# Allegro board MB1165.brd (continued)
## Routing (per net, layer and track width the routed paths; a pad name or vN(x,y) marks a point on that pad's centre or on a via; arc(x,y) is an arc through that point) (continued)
NETLD3_2: length 82.3
  TOP w0.127: R192.2 v1(72.77,48.13) ; LD3.2 v1(23.39,12.93)
  L3_SIG w0.102: v1(60.12,46.81) 60.58,46.35 68.45,46.35 69.72,47.62 72.26,47.62 v1(72.77,48.13)
  BOTTOM w0.127: v1(23.39,12.93) 23.6,12.73 26.9,12.73 28.7,10.92 42.16,10.92 46.99,15.75 46.99,21.59 51.56,26.16 55.98,26.16 58.45,28.63 58.45,32.41 58.09,32.77 58.09,36.84 60.5,39.25 60.5,46.43 v1(60.12,46.81)
NETLD4_2: length 82.5
  TOP w0.127: v1(21.31,12.98) LD4.2 ; R191.2 v1(70.99,48.13)
  L3_SIG w0.102: v1(70.99,48.13) 69.6,48.13 68.33,46.86 v1(60.96,46.86)
  BOTTOM w0.127: v1(60.96,46.86) 60.93,46.84 60.93,39.22 58.39,36.68 58.39,32.94 58.78,32.56 58.78,27.99 56.57,25.78 51.94,25.78 47.5,21.34 47.5,15.37 42.42,10.29 28.7,10.29 26.75,12.24 22.05,12.24 v1(21.31,12.98)
NETLD5_1: length 1.5
  TOP w0.127: LD5.1 R89.1
NETLD5_2: length 2.4
  TOP w0.254: LD5.2 v1(10.16,110.74)
  BOTTOM w0.254: T7.3 v1(10.16,110.74)
NETLD6_1: length 2.2
  TOP w0.508: LD6.1 v1(16,107.82)
  BOTTOM w0.508: v1(16,107.82) R279.1
NETLD6_2: length 21.9
  TOP w0.254: R112.2 24.14,101.09 25.67,102.62 26.69,102.62 27.2,103.12 U8.10
  TOP w0.508: v1(14.99,109.6) 15.75,110.36 LD6.2 17.09,111.45 U7.3 ; R112.2 R111.2 v1(22.86,102.49)
  L3_SIG w0.508: v1(22.86,102.49) 22.48,102.49 15.37,109.6 v1(14.99,109.6)
NETLD7_1: length 1.5
  TOP w0.127: R108.1 LD7.1
NETLD7_2: length 2.7
  TOP w0.254: v1(13.97,101.85) 13.72,101.85 LD7.2
  BOTTOM w0.254: T8.3 13.84,102.02 13.97,101.9 v1(13.97,101.85)
NETLD8_1: length 1.5
  TOP w0.127: R120.1 LD8.1
NETLD8_2: length 6.2
  TOP w0.508: 10.83,89.79 R121.2 11.43,90.4 ; 10.83,91.44 R119.2 ; R119.2 11.43,92.05 ; R119.2 11.43,90.83 ; LD8.2 9.54,91.44 ; LD8.2 8.89,90.83 ; LD8.2 8.89,92.05 ; 11.62,92.51 U11.3 12.14,93.29
NETLD9_1: length 1.5
  TOP w0.127: LD9.1 R122.1
NETLD9_2: length 2.9
  TOP w0.127: T2.3 13.8,85.51 LD9.2
NETLD10_1: length 1.5
  TOP w0.127: LD10.1 R130.1
NETLD11_1: length 1.7
  TOP w0.127: R187.2 LD11.1
NETLD11_2: length 58.1
  TOP w0.127: LD11.2 v1(13.34,16.51)
  TOP w0.508: U18.8 32.72,55.84 v1(32.64,55.75) 31.88,54.99 R144.2
  BOTTOM w0.127: v1(32.64,55.75) 30.78,53.9 30.78,45.09 33.27,42.6 33.27,33.91 31.5,32.13 31.5,30.07 25.91,24.49 25.91,21.23 21.69,17.02 13.84,17.02 v1(13.34,16.51)
NETLD12_2: length 1.9
  TOP w0.127: LD12.2 15,13.7 R188.2
NETLD12_3: length 1.9
  TOP w0.127: LD12.3 16.5,13.73 R189.2
NETLD12_4: length 5.3
  TOP w0.127: R190.1 17.78,10.45 LD12.4
NETR2_2: length 2.6
  TOP w0.508: U1.1 139.6,168.51 R2.2
NETR3_2: length 7.9
  TOP w0.127: SW1.2 49.53,166.37 46.23,166.37 44.96,167.64 R3.2
NETR6_1: length 7.9
  TOP w0.127: SW2.2 49.28,165.48 44.83,165.48 R6.1
NETR21_1: length 13.9
  TOP w0.127: R22.1 R21.1 84.58,147.57 84.58,144.82 v3(84.61,144.82) ; v5(81.21,140.09) U4.E5
  L3_SIG w0.102: v3(84.61,144.82) 84.6,144.82 84.58,144.81 84.58,142.96 82.87,141.24 82.59,141.24 82.4,141.05 82.4,140.72 82.17,140.49 81.61,140.49 v5(81.21,140.09)
NETR23_1: length 14.2
  TOP w0.102: 76.81,144.02 U4.K1
  TOP w0.127: 76.81,144.02 76.81,146.33 76.07,147.07 73.66,147.07 71.88,148.84 R23.1
NETR25_1: length 13.1
  TOP w0.127: U4.K2 76.73,142.09 76.45,142.37 76.45,142.72 76.44,142.73 76.44,143.04 76.45,143.05 76.45,144.02 76.07,144.4 74.93,144.4 71.75,147.57 67.31,147.57 R25.1
NETR26_1: length 3.1
  TOP w0.203: R26.1 137.47,146.56 X3.1
NETR27_1: length 12.3
  TOP w0.127: U4.L2 75.61,142.49 75.61,143.26 75.21,143.66 74.4,143.66 73.79,144.27 73.28,144.27 72.9,144.65 72.9,145.8 71.5,147.19 68.58,147.19 68.2,146.81 R27.1
NETR28_1: length 2.2
  TOP w0.127: R29.2 R28.1
NETR28_2: length 174.5
  TOP w0.127: v1(22.23,144.53) 16.64,144.53 R28.2
  L3_SIG w0.102: RV1.2 37.72,5.59 46.35,14.22 46.35,25.65 41.78,30.23 41.15,30.23 38.99,32.38 37.24,32.38 32.77,36.86 32.77,42.42 30.86,44.32 30.86,61.09 28.19,63.75 28.19,70.48 27.43,71.25 27.43,85.6 26.49,86.54 v1(26.49,92.43)
  BOTTOM w0.127: v1(26.49,92.43) 29.31,92.43 35.56,98.68 35.56,117.22 32,120.78 32,124.59 27.51,129.08 27.51,136.07 24.77,138.81 24.77,143.13 23.37,144.53 v1(22.23,144.53)
NETR32_1: length 13
  TOP w0.127: U4.B1 83.21,143.18 83.92,143.89 86.74,143.89 88.77,145.92 R32.1 89.79,146.56 89.66,146.69 SB3.2 SB4.2 SB5.2
NETR34_1: length 81.5
  TOP w0.127: v1(127.06,102.43) 127.19,102.43 SB18.2 SB19.2 129.57,101.63 129.57,103.1 SB17.2 ; U4.B2 83.21,142.37 83.58,142.73 83.58,143.01 83.95,143.38 87.12,143.38 88.39,144.65 R34.1 90.42,145.29 91.06,145.29 91.95,146.18 99.95,146.18 v1(100.2,145.92)
  L3_SIG w0.102: v1(127.06,102.43) 125.54,102.43 120.14,107.82 116.08,107.82 105.41,118.49 v1(105.28,118.49)
  BOTTOM w0.127: v1(100.2,145.92) 100.36,145.92 100.97,145.31 100.97,134.24 104.27,130.94 104.27,124.46 105.28,123.44 v1(105.28,118.49)
NETR35_1: length 11.1
  TOP w0.127: SB6.2 93.47,143.76 ; U4.A1 88.96,142.89 89.46,143.38 R35.1 90.3,143.89 93.09,143.89 93.22,143.76
NETR37_1: length 13.4
  TOP w0.127: 93.47,140.44 92.86,140.44 91.72,141.58 90.02,141.58 89.53,141.1 SB9.2 89.53,140.59 89.66,140.46 R37.1 89.25,139.19 86.74,141.7 84.82,141.7 84.43,142.09 U4.A2
NETR38_1: length 32.4
  TOP w0.127: U4.A3 84.04,141.32 86.52,141.32 88.33,139.51 88.33,139.26 R38.1 90.17,138.43 91.57,138.43 91.85,138.71 SB11.2 93.47,138.35 93.94,137.88 97.96,137.88 v1(98.93,136.91)
  L3_SIG w0.102: v1(111.82,137.97) 107.75,137.97 106.68,136.91 v1(98.93,136.91)
  BOTTOM w0.127: R238.2 111.24,138.56 v1(111.82,137.97)
NETR40_1: length 8.2
  TOP w0.127: U4.B6 83.58,139.26 84.16,139.26 84.23,139.19 84.81,139.19 84.93,139.06 86.08,139.06 86.41,138.73 86.41,137.92 86.64,137.69 87.17,137.69 88.14,136.73 88.72,136.73 88.93,136.53 R40.1
NETR41_1: length 9.4
  TOP w0.127: U4.B7 83.63,138.51 84.38,138.51 85.5,137.39 87.02,137.39 88.09,136.32 88.09,135.15 88.52,134.72 88.52,134.49 89.03,133.99 R41.1
NETR42_1: length 3.1
  TOP w0.127: R42.1 124.71,128.4 125.35,127.76 125.48,127.76 126.27,126.97 U6.46
NETR43_1: length 2.7
  TOP w0.127: U6.45 126.77,127.23 125.98,128.02 R43.1
NETR43_2: length 20.7
  TOP w0.127: v1(124.61,140.39) 124.61,136.37 125.35,135.64 125.35,130.68 R43.2
  L3_SIG w0.102: v1(124.61,140.39) 120.7,140.39 v1(117.35,137.03)
  BOTTOM w0.127: v1(117.35,137.03) 116.94,137.44 SB55.2
NETR44_1: length 2.4
  TOP w0.127: U6.44 127.27,128.51 R44.1
NETR44_2: length 127.5
  TOP w0.127: R44.2 125.83,131.47 125.83,136.58 125.35,137.06 125.35,156.24 125.83,156.72 125.83,157.89 v1(125.09,158.62)
  L3_SIG w0.102: v1(102.36,157.61) 102.87,157.61 103.89,158.62 v1(125.09,158.62)
  BOTTOM w0.127: SB73.2 48.73,130.14 48.73,131.1 50.7,133.07 50.7,138.41 55.41,143.12 55.41,148.76 60.48,153.83 64.8,153.83 68.2,157.23 69.47,157.23 70.15,157.91 80.52,157.91 80.92,158.32 93.42,158.32 93.83,158.72 101.24,158.72 v1(102.36,157.61)
NETR45_1: length 2.7
  TOP w0.127: R45.1 128.52,127.89 127.76,127.13 127.76,126.15 U6.43
NETR45_2: length 147.3
  TOP w0.127: R45.2 126.36,132.21 126.36,152.43 v1(126.85,152.91)
  BOTTOM w0.127: SB53.2 37.47,142.9 36.83,143.54 36.83,158.5 42.04,163.7 42.04,167 44.32,169.29 86.61,169.29 87.12,168.78 87.63,168.78 88.14,169.29 110.46,169.29 v1(126.85,152.91)
NETR46_1: length 2.6
  TOP w0.127: U6.39 129.77,127.1 130.18,127.51 R46.1
NETR46_2: length 113.6
  TOP w0.127: v1(127.83,132.84) 128.84,131.83 129.16,131.83 130.18,130.81 R46.2
  BOTTOM w0.127: SB45.1 49.02,144.53 51.61,147.12 51.61,150.42 59.94,158.75 63.37,158.75 66.42,161.8 82.14,161.8 83.16,160.78 91.59,160.78 92.46,161.65 97.77,161.65 98.42,162.31 105.08,162.31 107.95,159.44 113.36,159.44 119.13,153.67 119.13,152.4 127.64,143.89 127.64,133.03 v1(127.83,132.84)
NETR47_1: length 2.9
  TOP w0.127: R47.1 131.44,128.27 130.27,127.09 U6.38
NETR47_2: length 111.8
  TOP w0.127: v1(128.14,134.11) 128.14,133.81 131.44,130.51 R47.2
  BOTTOM w0.127: v1(128.14,134.11) 128.14,144.15 119.63,152.65 119.63,154.05 113.23,160.45 109.25,160.45 106.32,163.37 65.07,163.37 64.39,162.69 61.85,162.69 61.34,162.18 58.55,162.18 49.35,152.98 49.35,150.95 SB39.1
NETR48_1: length 16.8
  TOP w0.127: U4.P8 73.23,137.67 70.51,137.67 64.52,131.67 R48.1
NETR49_1: length 15.4
  TOP w0.127: R49.1 65.53,131.59 70.85,136.91 71.79,136.91 71.8,136.92 73.18,136.92 U4.P9
NETR50_1: length 14.8
  TOP w0.127: R50.1 66.55,131.53 71.11,136.09 74.01,136.09 U4.N9
NETR51_1: length 12.6
  TOP w0.127: R51.1 67.56,131.47 71.38,135.29 73.21,135.29 U4.P10
NETR52_1: length 10.9
  TOP w0.127: U4.P11 73.22,134.49 72.64,134.49 71.88,133.73 71.45,133.73 68.58,130.86 R52.1
NETR53_2: length 7
  TOP w0.127: R53.2 70.99,128.12 72.64,129.77 72.64,130.94 73.21,131.5 73.21,132.09 U4.P14
NETR54_2: length 6.7
  TOP w0.127: U4.N14 74.02,132.09 74.02,131.29 73.41,130.68 73.41,129.22 72.39,128.21 R54.2
NETR55_2: length 5.7
  TOP w0.127: U4.M15 75.21,130.58 74.17,129.54 74.17,128.91 73.79,128.52 R55.2
NETR56_1: length 5.6
  TOP w0.127: R56.1 74.96,126.85 74.96,129.19 76.01,130.24 U4.L15
NETR57_1: length 2.2
  TOP w0.127: R57.1 121.92,124.46 122,124.54 U6.1
NETR57_2: length 115.7
  TOP w0.127: v1(120.65,137.03) 120.65,136.09 121.54,135.2 R57.2
  BOTTOM w0.127: v1(120.65,137.03) 117.2,140.49 113.31,140.49 112.36,141.44 111.75,141.44 110.62,142.57 110.62,154.18 107.89,156.91 107.89,158.31 104.9,161.29 98.81,161.29 98.37,160.86 92.61,160.86 91.85,160.1 81.76,160.1 81.1,160.76 77.32,160.76 76.63,160.07 68.4,160.07 68.05,159.72 66.42,159.72 63.3,156.59 60.07,156.59 53.16,149.68 53.16,144.18 48.88,139.79 48.88,139.43 SB54.2
NETR58_1: length 18.6
  TOP w0.127: R58.1 65.02,123.83 65.02,131.62 70.69,137.29 U4.R8
NETR59_1: length 17.3
  TOP w0.127: U4.R9 72.48,136.49 72.44,136.53 71,136.53 66.04,131.56 66.04,123.83 R59.1
NETR60_1: length 15.9
  TOP w0.127: R60.1 67.06,123.83 67.06,131.5 71.24,135.69 U4.R10
NETR61_1: length 14.2
  TOP w0.127: R61.1 68.07,123.83 68.07,130.94 71.37,134.24 72.01,134.24 72.66,134.89 U4.R11
NETR62_1: length 12.8
  TOP w0.127: U4.R12 72.07,133.35 71.68,133.35 69.01,130.68 69.01,129.03 69.09,128.96 69.09,123.83 R62.1
NETR63_2: length 9.5
  TOP w0.127: U4.P15 73.61,131.39 73.03,130.81 73.03,129.49 71.5,127.97 71.5,124.59 70.99,124.08 R63.2
NETR64_2: length 9.2
  TOP w0.127: R64.2 72.39,123.83 72.9,124.33 72.9,128.18 73.79,129.07 73.79,130.57 74.41,131.19 U4.N15
NETR65_1: length 10.1
  TOP w0.127: R65.1 73.79,123.95 74.3,124.46 74.3,128.49 74.55,128.75 74.55,129.38 75.62,130.45 75.62,132.09 U4.L14
NETR66_1: length 9.4
  TOP w0.127: U4.K15 76.82,131.67 76.82,130.29 75.41,128.88 75.41,127.56 75.82,127.16 75.82,123.95 R66.1
NETR67_1: length 3
  TOP w0.254: R67.1 135.02,123.04 U6.33
NETR68_2: length 127
  TOP w0.127: U6.7 121.54,121.54 R68.2 v1(122.28,120.8) ; v1(58.04,43.18) 58.51,42.71 U22.26
  L3_SIG w0.102: v1(58.04,43.18) 60.1,45.24 79.12,45.24 82.91,49.02 83.74,49.02 100.79,66.07 100.79,69.39 102.55,71.16 105.4,71.16 107.54,73.3 107.54,75.16 109.73,77.34 109.73,81.15 110.29,81.71 110.29,87.73 116.38,93.83 v1(116.38,94.03)
  BOTTOM w0.127: v1(116.38,94.03) 116.23,94.18 116.23,112.14 123.04,118.95 123.04,120.29 122.53,120.8 v1(122.28,120.8)
NETR69_1: length 138.2
  TOP w0.127: U6.30 133.22,121.54 v1(133.6,121.16) 134.11,121.16 R69.1
  BOTTOM w0.127: v1(133.6,121.16) 134.11,121.67 134.11,122.68 133.1,123.7 133.1,126.44 129.59,129.95 129.59,145.14 113.18,161.54 109.98,161.54 107.44,164.08 64.77,164.08 64.14,163.45 57.28,163.45 51.94,158.12 42.29,158.12 38.99,154.81 38.99,150.6 SB40.1
NETR71_1: length 4.4
  TOP w0.127: R71.1 134.24,118.24 134.24,118.77 132.97,120.04 U6.27
NETR74_2: length 4.7
  TOP w0.254: R74.2 R78.1 v1(12.95,111.25)
  BOTTOM w0.254: T7.1 12.51,111.69 v1(12.95,111.25)
NETR75_1: length 2.6
  TOP w0.127: R75.1 128.77,116.07 U6.20
NETR76_1: length 2.3
  TOP w0.127: R76.1 129.27,115.21 U6.21
NETR77_2: length 3.4
  TOP w0.127: R77.2 132.08,117.19 131.83,117.44 U6.24
NETR82_1: length 5.1
  TOP w0.127: R82.1 33.27,109.98 32.26,109.98 31.62,109.35 31.62,108.2 31.21,107.8 U8.24
NETR84_1: length 7.2
  TOP w0.102: 76.45,107.95 76.45,105.83 U9.F2
  TOP w0.127: R84.1 R85.1 76.45,109.98 76.45,107.95
NETR88_2: length 5.8
  TOP w0.508: U7.4 19.87,112.59 20.57,111.89 SB16.2 R88.2 SB15.2
NETR91_2: length 2.6
  TOP w0.127: R91.2 26.58,108.58 U8.32
NETR94_1: length 3.4
  TOP w0.127: R94.1 33.52,106.29 U8.21
NETR95_1: length 2
  TOP w0.254: U8.4 24.39,106.29 R95.1
NETR97_2: length 5.5
  TOP w0.254: v1(12.95,106.68) R97.2 R100.2
  BOTTOM w0.254: T8.1 11.75,105.48 v1(12.95,106.68)
NETR98_1: length 3.3
  TOP w0.127: R98.1 33.78,105.8 U8.20
NETR99_1: length 66.2
  TOP w0.102: v4(82.68,102.37) U9.A5 ; v5(63.79,72.16) U16.G5
  TOP w0.127: v1(86.87,103.38) R99.1
  L3_SIG w0.102: v4(82.68,102.37) 83.3,102.99 86.48,102.99 v1(86.87,103.38)
  BOTTOM w0.127: v5(63.79,72.16) 63.42,72.53 62.47,72.53 61.75,73.25 61.75,75.54 61.87,75.67 63.12,75.67 63.25,75.79 63.25,90.4 63.37,90.53 64.89,90.53 65.02,90.65 65.02,100.61 73.38,108.97 79.15,108.97 80.48,107.63 80.48,106.14 80,105.66 80,104.7 82.34,102.37 v4(82.68,102.37)
NETR101_2: length 10
  TOP w0.127: U8.9 25.53,103.62 25.03,103.12 22.35,103.12 21.46,104.01 R101.2 18.8,103.63 18.8,103.21 18.29,102.7 T1.3
NETR109_1: length 4.5
  TOP w0.127: R109.1 32.38,103.63 32.38,104.27 31.86,104.8 U8.18
NETR111_1: length 99.8
  TOP w0.127: v1(26.57,96.11) 25.3,96.11 22.86,98.55 R111.1 ; U22.29 57.02,37.99 57.02,36.96 56.59,36.53 56.59,33.39 v1(57.02,32.96)
  L3_SIG w0.102: v1(57.02,32.96) 57.02,32.89 56.69,32.56 52.37,32.56 49.73,29.92 44.6,29.92 40.26,34.26 38,34.26 34.42,37.85 34.42,44.58 33.66,45.34 33.66,61.21 32.05,62.81 32.05,69.55 29.18,72.42 29.18,93.5 v1(26.57,96.11)
NETR113_1: length 2.9
  TOP w0.127: R113.1 29.97,101.22 29.2,101.99 U8.14
NETR114_1: length 5.5
  TOP w0.127: T1.1 17.34,98.87 R115.2 18.29,97.92 19.94,97.92 R114.1
NETR116_2: length 6.2
  TOP w0.508: R116.2 12.29,97.28 ; R116.2 11.07,97.28 ; R116.2 11.68,96.68 ; U11.4 12.14,95.69 ; U11.4 11.1,95.69 ; U11.4 11.62,94.91 ; U11.4 11.62,96.46 ; 13.21,96.68 R117.1 ; R117.1 12.6,97.28 ; R117.1 13.82,97.28
NETR117_2: length 106.8
  TOP w0.127: U22.17 58.76,32.9 v1(57.99,32.13) ; R117.2 v1(14.99,98.81)
  L3_SIG w0.102: v1(14.99,98.81) 22.99,98.81 28.91,92.89 28.91,72.3 31.72,69.48 31.72,62.76 33.4,61.09 33.4,45.21 34.16,44.45 34.16,37.72 37.85,34.04 40.11,34.04 44.55,29.59 53.85,29.59 56.52,32.26 57.86,32.26 v1(57.99,32.13)
NETR119_1: length 100.8
  TOP w0.127: U22.16 59.02,32.41 v1(57.99,31.37) ; R119.1 14.15,91.44 18.29,87.3 v1(28.09,87.3)
  L3_SIG w0.102: v1(28.09,87.3) 28.6,86.79 28.6,72.19 31.39,69.39 31.39,62.71 32.13,61.98 32.13,45.85 33.91,44.07 33.91,37.59 37.74,33.76 39.98,33.76 44.42,29.31 54.08,29.31 56.64,31.88 57.48,31.88 v1(57.99,31.37)
NETR126_2: length 6.7
  TOP w0.127: T2.1 10.67,83.84 10.67,82.42 11.43,81.66 R127.2 R126.2
NETR134_1: length 7.8
  TOP w0.102: U16.B5 68.29,72.16 68.29,71.54 68.71,71.12 68.71,69.09
  TOP w0.127: R135.1 R134.1 68.71,66.8 68.71,69.09
NETR140_1: length 1.6
  TOP w0.254: R140.1 39.12,58.29 R141.2
NETR140_2: length 2.3
  TOP w0.254: R140.2 37.49,57.68 U18.5
NETR142_1: length 126.1
  TOP w0.127: v1(58.98,35.26) 57.51,36.72 U22.28 ; R142.1 141.86,55.88 139.83,53.85 R143.1 138.94,53.98 138.15,54.76 v1(133.4,54.76)
  BOTTOM w0.127: v1(133.4,54.76) 133.4,47.55 126.75,40.89 126.75,23.22 125.76,22.23 110.49,22.23 102.87,29.84 70.99,29.84 69.6,31.24 61.34,31.24 60.33,32.26 60.33,33.63 58.98,34.98 v1(58.98,35.26)
NETR155_1: length 2
  TOP w0.127: R155.1 62.12,34.9 U22.21
NETR155_2: length 2.1
  TOP w0.127: R155.2 61.82,35.41 U22.22
NETR156_1: length 2.5
  TOP w0.127: R156.1 50.68,32.9 U22.44
NETR157_2: length 2.9
  TOP w0.127: R157.2 32.9,32.9 U21.44
NETR158_1: length 4.3
  TOP w0.127: R159.1 49.78,29.84 R158.1 50.42,31.62 50.42,32.13 50.69,32.41 U22.45
NETR163_1: length 5.4
  TOP w0.127: R163.1 51.05,27.3 51.31,27.05 R164.2 52.2,27.05 52.2,27.43 52.96,28.19 53.63,28.19 54.01,28.57 U22.2
NETR163_2: length 160.6
  TOP w0.127: v1(47.24,30.99) 47.24,28.5 49.58,26.16 49.91,26.16 R163.2 50.29,25.4 57.02,18.67 57.02,11.05
  L3_SIG w0.102: v1(36.96,119.38) 37.21,119.63 37.21,123.44 34.8,125.86 34.8,137.92 35.43,138.56 35.43,144.25 36.2,145.01 36.2,145.85 37.72,147.37 v1(39.1,147.37)
  BOTTOM w0.127: SB44.1 40.51,145.96 v1(39.1,147.37) ; v1(47.24,30.99) 51.94,35.69 51.94,39.62 59.41,47.09 59.41,60.43 48.69,71.15 48.69,78.38 39.27,87.81 39.27,107.21 37.39,109.09 37.39,118.95 v1(36.96,119.38)
NETR167_2: length 3.5
  TOP w0.127: R167.2 33.54,27.18 34.56,28.19 35.31,28.19 35.72,28.61 U21.2
NETR168_2: length 2.7
  TOP w0.127: U21.3 36.22,28.6 R168.2
NETR171_1: length 9.9
  TOP w0.127: U23.D4 117.86,28.58 v2(118.11,28.83) U23.D5 ; R171.1 124.26,25.22 v1(124.26,25.02)
  L3_SIG w0.102: v1(124.26,25.02) 123.04,25.02 120.37,27.69 118.76,27.69 118.44,28 118.44,28.5 v2(118.11,28.83)
NETR172_2: length 9.5
  TOP w0.127: U23.F3 v2(119.11,28.33) ; v1(125.86,25.27) 126.11,25.27 R172.2
  L3_SIG w0.102: v2(119.11,28.33) 119.48,27.97 120.9,27.97 123.14,25.73 125.4,25.73 v1(125.86,25.27)
NETR178_2: length 5
  TOP w0.127: U23.G2 v2(119.61,27.33) ; R178.2 122.43,24.82 v1(122.4,24.85)
  L3_SIG w0.102: v1(122.4,24.85) 119.92,27.33 v2(119.61,27.33)
NETR179_2: length 5.5
  TOP w0.127: R179.2 123.83,24.38 121.13,27.08 U23.H1
NETR182_2: length 2.2
  TOP w0.127: T4.2 18.99,21.53 18.54,21.08 R182.2
NETR186_1: length 3.4
  TOP w0.127: R186.1 122.43,15.49 122.43,16 122.68,16.26 123.19,16.26 123.78,15.66 U25.2
NETR214_2: length 19.5
  TOP w0.102: U4.H3 77.99,140.87 v5(77.22,140.87)
  BOTTOM w0.127: R214.2 67.94,152.27 74.17,146.05 74.17,145.67 75.06,144.78 75.07,144.78 75.44,144.41 75.44,143 75.18,142.75 75.18,141.59 75.46,141.32 75.75,141.32 76.04,141.03 76.04,140.73 76.29,140.49 76.94,140.49 77.22,140.77 v5(77.22,140.87)
NETR216_1: length 3.7
  TOP w0.127: U3.8 v1(32.89,152.78)
  BOTTOM w0.127: R216.1 v1(32.89,152.78)
NETR217_2: length 4.2
  TOP w0.127: v1(28.96,152.78) U3.9
  BOTTOM w0.127: R217.2 v1(28.96,152.78)
NETR221_1: length 18.1
  TOP w0.127: v5(76.41,141.69) U4.K3
  BOTTOM w0.127: v5(76.41,141.69) 76.41,141.75 77.09,143.32 77.09,144.94 78.33,146.18 83.57,146.18 85.09,147.7 89.03,147.7 R221.1
NETR222_1: length 8.4
  TOP w0.127: v5(73.66,145.03) 74.68,144.02 75.56,144.02 76.01,143.57 U4.L1
  BOTTOM w0.127: v5(73.66,145.03) 73.66,145.16 R222.1
NETR223_1: length 15.9
  TOP w0.127: v5(77.21,142.49) U4.J2
  BOTTOM w0.127: R223.1 89.66,147.32 85.34,147.32 83.82,145.8 80.84,145.8 80.14,145.1 80.14,144.23 79.46,143.56 77.93,143.56 77.21,142.84 v5(77.21,142.49)
NETR226_1: length 15.7
  TOP w0.127: U4.H2 78.36,142.09 v5(77.99,142.46)
  BOTTOM w0.127: R226.1 89.28,145.92 88.27,146.94 85.6,146.94 84.02,145.36 80.94,145.36 80.52,144.94 80.52,144.08 79.65,143.21 78.05,143.21 77.85,143 77.85,142.6 v5(77.99,142.46)
NETR227_1: length 4.1
  TOP w0.127: v1(32.41,145.03) 32.64,145.03 33.78,143.89 U3.1
  BOTTOM w0.127: v1(32.41,145.03) R227.1
NETR228_2: length 4.2
  TOP w0.127: U3.15 28.7,145.16 v1(28.83,145.03)
  BOTTOM w0.127: R228.2 v1(28.83,145.03)
NETR230_1: length 12.9
  TOP w0.127: v5(79.61,142.49) U4.G2
  BOTTOM w0.127: v5(79.61,142.49) 79.61,142.5 80.9,143.79 80.9,144.78 81.09,144.97 83.8,144.97 84.14,144.64 84.14,144.59 84.5,144.23 89.37,144.23 R230.1
NETR232_1: length 10.3
  TOP w0.127: v5(81.21,142.49) U4.E2
  BOTTOM w0.127: R232.1 88.56,142.24 87,143.81 84.14,143.81 83.64,143.31 82.6,143.31 82.19,142.9 81.86,142.9 81.45,142.49 v5(81.21,142.49)
NETR233_2: length 143.4
  TOP w0.127: v1(122.1,155.57) 122.1,142.52 119.91,140.34 119.91,124.13 120.62,123.42 120.62,122.96 121.04,122.54 U6.5
  BOTTOM w0.127: R233.2 37.85,143.89 37.85,155.45 42.04,159.64 51.31,159.64 58.17,166.5 110.74,166.5 121.67,155.57 v1(122.1,155.57)
NETR235_2: length 29
  TOP w0.127: U6.4 122.68,123.04 122.52,122.89 121.46,122.89 v1(121.08,123.27)
  BOTTOM w0.127: v1(121.08,123.27) 121.34,123.52 121.34,127.13 120.52,127.94 120.52,134.78 119.33,135.97 119.33,137.11 117.35,139.09 111.89,139.09 111.38,139.6 109.83,139.6 R235.2
NETR236_1: length 11.2
  TOP w0.127: v5(82.01,142.49) U4.D2
  BOTTOM w0.127: R236.1 89.66,139.32 87.5,141.48 87.5,142.75 86.82,143.43 84.12,143.43 83.72,143.03 82.78,143.03 82.24,142.49 v5(82.01,142.49)
NETR237_1: length 10.2
  TOP w0.127: U4.L3 v5(75.61,141.69)
  L3_SIG w0.102: v1(68.2,139.7) 69.09,140.59 72.14,140.59 72.82,141.27 75.23,141.27 75.61,141.65 v5(75.61,141.69)
  BOTTOM w0.127: v1(68.2,139.7) 67.56,139.06 R237.1
NETR238_1: length 30
  TOP w0.127: U6.6 122.76,122.04 122.66,122.15 120.83,122.15 120.14,122.83 v1(120.14,123.19)
  BOTTOM w0.127: v1(120.14,123.19) 120.14,123.88 120.9,124.64 120.9,127.02 120.14,127.78 120.14,134.62 118.71,136.06 118.71,137.07 117.07,138.71 111.71,138.71 111.2,139.22 109.88,139.22 R238.1
NETR239_2: length 11.8
  TOP w0.127: v5(75.61,140.09) U4.L5
  BOTTOM w0.127: R239.2 67.31,137.79 70.26,140.74 73.3,140.74 73.86,141.3 74.96,141.3 75.23,141.02 75.23,140.72 75.61,140.34 v5(75.61,140.09)
NETR240_2: length 10.5
  TOP w0.127: v5(82.01,140.89) U4.D4
  BOTTOM w0.127: R240.2 89.59,137.03 88.39,138.23 88.39,138.84 87.26,139.97 84.44,139.97 83.13,141.27 82.4,141.27 v5(82.01,140.89)
NETR241_2: length 11.6
  TOP w0.127: v5(81.21,140.89) U4.E4
  BOTTOM w0.127: R241.2 88.42,137.26 88.42,137.62 88.01,138.02 88.01,138.66 87.08,139.59 83.93,139.59 83.06,140.46 81.63,140.46 v5(81.21,140.89)
NETR242_2: length 17.9
  TOP w0.127: U6.2 122.39,124.04 122.17,123.83 120.95,123.83 120.41,124.37 v1(120.41,125.3)
  BOTTOM w0.127: R242.2 118.11,135.89 119.76,134.24 119.76,127.56 120.41,126.91 v1(120.41,125.3)
NETR243_2: length 17.3
  TOP w0.127: v5(77.24,140.08) 77.61,140.45 U4.J4
  BOTTOM w0.127: SB63.1 65.02,135.89 66.67,135.89 R243.2 69.47,137.67 69.47,139.32 70.64,140.49 74.96,140.49 75.18,140.26 75.18,139.95 75.44,139.7 76.56,139.7 76.94,140.08 v5(77.24,140.08)
NETR244_2: length 12.9
  TOP w0.127: SB12.1 88.57,136.22 v1(88.54,136.22) ; U4.D5 v5(82.01,140.09)
  BOTTOM w0.127: R244.2 89.03,135 88.54,135.48 v1(88.54,136.22) 87.6,137.16 87.6,138.51 86.91,139.2 83.43,139.2 82.93,139.7 82.4,139.7 v5(82.01,140.09)
NETR245_1: length 11.4
  TOP w0.127: v5(74.01,139.29) U4.N6
  BOTTOM w0.127: v5(74.01,139.29) 73.77,139.29 73.2,139.85 71.09,139.85 70.36,139.12 70.36,138.81 70.36,137.44 69.09,136.17 69.09,135.41 67.79,134.11 R245.1
NETR246_2: length 21
  TOP w0.127: v5(77.21,141.69) U4.J3
  BOTTOM w0.127: v5(77.21,141.69) 77.62,141.27 77.62,139.9 77.43,139.71 77.03,139.71 76.83,139.52 76.83,139.09 76.63,138.89 75.46,138.89 75.21,139.14 75.21,139.47 74.98,139.7 73.81,139.7 73.28,140.23 70.93,140.23 69.86,139.17 69.86,137.55 68.69,136.39 68.69,135.62 67.82,134.75 65.79,134.75 65.15,134.11 R246.2
NETR247_2: length 12
  TOP w0.127: v5(82.01,139.29) U4.D6
  BOTTOM w0.127: v5(82.01,139.29) 82.38,138.91 83.08,138.91 83.17,138.82 86.7,138.82 87.22,138.3 87.22,136.88 88.01,136.09 88.01,134.87 88.9,133.99 R247.2
NETR248_1: length 11.9
  TOP w0.127: v5(74.81,139.29) U4.M6
  BOTTOM w0.127: v5(74.81,139.29) 74.38,138.86 73.86,138.86 73.28,138.28 73.28,137.32 72.99,137.03 71.06,137.03 69.98,135.95 69.98,135.13 67.69,132.84 R248.1
NETR249_1: length 13.5
  TOP w0.127: v5(73.21,139.29) U4.P6
  BOTTOM w0.102: v5(73.21,139.29) 73.03,139.47 71.63,139.47
  BOTTOM w0.127: 71.63,139.47 71.25,139.47 70.74,138.96 70.74,137.29 69.47,136.02 69.47,135.25 67.56,133.35 65.79,133.35 65.28,132.84 R249.1
NETR250_1: length 12.3
  TOP w0.127: v5(74.81,138.49) U4.M7
  BOTTOM w0.127: R250.1 67.82,131.44 70.74,134.37 70.74,135.64 71.37,136.27 72.87,136.27 73.79,137.19 73.79,137.95 73.95,138.11 74.44,138.11 v5(74.81,138.49)
NETR251_1: length 14
  TOP w0.127: v5(74.01,138.49) U4.N7
  BOTTOM w0.127: R251.1 65.28,131.44 66.04,132.21 67.69,132.21 70.36,134.87 70.36,135.79 71.22,136.65 72.93,136.65 73.53,137.25 73.53,138.05 73.97,138.49 v5(74.01,138.49)
NETR254_1: length 67
  BOTTOM w0.127: SB27.2 92.61,156.16 91.54,157.23 81.76,157.23 81.38,156.84 70.99,156.84 69.7,155.55 67.92,155.55 65.38,153.01 60.93,153.01 56.18,148.26 56.18,142.8 51.51,138.13 51.51,130.51 48.51,127.51 R254.1
NETR256_1: length 11.2
  TOP w0.127: v5(76.38,133.71) 76.8,133.29 U4.K13
  BOTTOM w0.127: v5(76.38,133.71) 76.38,133.86 76.02,134.21 76.02,134.6 75.76,134.86 75.42,134.86 75.18,134.62 75.18,133.53 75.46,133.25 75.46,132.31 75.41,132.26 75.41,127.53 R256.1
NETR257_1: length 8.1
  TOP w0.127: v5(74.81,133.69) U4.M12
  BOTTOM w0.127: R257.1 74.88,126.92 74.88,132.13 75.2,132.45 75.2,133.06 74.81,133.44 v5(74.81,133.69)
NETR258_1: length 9
  TOP w0.127: v5(74.81,134.49) U4.M11
  BOTTOM w0.127: v5(74.81,134.49) 74.42,134.1 74.42,132.72 73.6,131.9 73.6,126.8 R258.1
NETR259_1: length 9.2
  TOP w0.127: v5(74.01,134.49) U4.N11
  BOTTOM w0.127: R259.1 72.39,128.4 72.84,128.85 72.84,133.04 73.12,133.32 73.36,133.32 73.64,133.6 73.64,134.12 v5(74.01,134.49)
NETR260_2: length 10.8
  TOP w0.127: v5(74.01,135.29) U4.N10
  BOTTOM w0.127: v5(74.01,135.29) 73.82,135.29 71.63,133.1 71.63,130.68 71.88,130.43 71.88,129.16 70.99,128.27 R260.2
NETR261_1: length 14.1
  TOP w0.102: U4.M8 75.21,137.29 v5(75.61,136.89)
  BOTTOM w0.127: R261.1 68.58,130.43 74.67,136.52 75.24,136.52 v5(75.61,136.89)
NETR262_1: length 9.1
  TOP w0.127: v5(83.61,133.69) U4.B12
  BOTTOM w0.127: v5(83.61,133.69) 84.05,133.24 84.05,131.46 84.98,130.54 84.98,128.82 86.23,127.56 R262.1
NETR263_2: length 7.3
  TOP w0.127: v5(82.81,132.09) U4.C14
  BOTTOM w0.127: R263.2 84.39,126.69 84.39,127.58 82.81,129.15 v5(82.81,132.09)
NETR264_2: length 7
  TOP w0.127: v5(82.01,132.09) U4.D14
  BOTTOM w0.127: R264.2 83.44,126.54 82.01,127.97 v5(82.01,132.09)
NETR265_2: length 6.8
  TOP w0.127: v5(81.21,132.09) U4.E14
  BOTTOM w0.127: R265.2 82.04,126.75 81.21,127.58 v5(81.21,132.09)
NETR266_2: length 8.4
  TOP w0.127: v5(81.21,133.69) U4.E12
  BOTTOM w0.127: R266.2 80.52,126.36 80.52,127.19 80.45,127.26 80.45,132.39 80.8,132.74 80.8,133.27 v5(81.21,133.69)
NETR267_1: length 7.4
  TOP w0.127: v1(79.84,127.92) 79.6,127.92 78.32,129.2 78.32,130.85 77.98,131.19 77.98,132.06 U4.H14
  BOTTOM w0.127: v1(79.84,127.92) 79.84,126.45 R267.1
NETR268_1: length 11.7
  TOP w0.127: U4.L12 v5(75.61,133.69)
  BOTTOM w0.127: R268.1 76.45,123.37 76.96,123.88 76.96,126.87 76.45,127.38 76.45,128.95 75.82,129.58 75.82,132.26 75.73,132.35 75.73,133.36 75.61,133.48 v5(75.61,133.69)
NETR269_1: length 10.8
  TOP w0.127: v5(74.81,132.89) U4.M13
  BOTTOM w0.127: R269.1 73.79,123.61 74.3,124.11 74.3,127.69 74.02,127.97 74.02,131.88 74.81,132.67 v5(74.81,132.89)
NETR270_1: length 11.6
  TOP w0.127: v5(74.01,133.69) U4.N12
  BOTTOM w0.127: R270.1 72.39,123.92 72.9,124.43 72.9,128.27 73.22,128.59 73.22,132.05 73.58,132.4 73.58,133.14 74.01,133.57 v5(74.01,133.69)
NETR271_1: length 14.7
  TOP w0.127: v5(74.81,135.29) U4.M10
  BOTTOM w0.127: R271.1 70.99,124.14 71.5,124.65 71.5,128.14 72.26,128.91 72.26,130.81 71.88,131.19 71.88,132.88 73.88,134.87 74.4,134.87 v5(74.81,135.29)
NETR273_1: length 12.7
  TOP w0.127: v5(82.81,133.69) U4.C12
  BOTTOM w0.127: v5(82.81,133.69) 83.19,133.31 83.19,131.83 84.6,130.42 84.6,128.6 85.39,127.8 85.39,124.89 84.84,124.33 R273.1
NETR274_2: length 11.6
  TOP w0.127: v5(82.81,132.89) U4.C13
  BOTTOM w0.127: v5(82.81,132.89) 82.42,132.5 82.42,128.91 83.95,127.38 83.95,123.19 R274.2
NETR275_2: length 11.4
  TOP w0.127: v5(82.01,132.89) U4.D13
  BOTTOM w0.127: R275.2 82.55,123.32 82.55,126.87 81.64,127.79 81.64,127.88 81.63,127.89 81.63,130.71 81.64,130.72 81.64,132.51 v5(82.01,132.89)
NETR276_2: length 11.1
  TOP w0.127: v5(81.21,132.89) U4.E13
  BOTTOM w0.127: R276.2 80.64,123.83 81.15,124.33 81.15,127 80.9,127.25 80.9,127.35 80.83,127.42 80.83,132.39 81.21,132.77 v5(81.21,132.89)
NETR282_1: length 3.7
  TOP w0.102: v5(76.71,97.79) 76.5,97.99 76.5,99.97 U9.F7
  BOTTOM w0.102: R282.1 v5(76.71,97.79)
NETR285_1: length 3.2
  TOP w0.102: v5(89.86,76.96) U15.J2
  BOTTOM w0.102: 90.41,78.21 90.32,78.13 90.32,77.42 v5(89.86,76.96)
  BOTTOM w0.127: R285.1 90.93,78.36 90.55,78.36 90.41,78.21
NETR287_2: length 2.4
  TOP w0.127: U22.42 52.7,33.9 v1(53.09,34.29)
  BOTTOM w0.127: v1(53.09,34.29) 53.59,34.29 R287.2
NETR288_2: length 2.1
  TOP w0.127: v1(53.09,33.4) 52.59,33.4 52.58,33.41 U22.43
  BOTTOM w0.127: v1(53.09,33.4) R288.2
NETR289_2: length 2.7
  TOP w0.127: U21.20 v1(43.43,34.41)
  BOTTOM w0.127: R289.2 42.43,33.4 v1(43.43,34.41)
NETR290_2: length 2.2
  TOP w0.127: v1(53.09,32.13) 52.83,32.13 52.61,31.9 U22.46
  BOTTOM w0.127: R290.2 v1(53.09,32.13)
NETR292_1: length 4.3
  TOP w0.127: T4.1 21.48,21.08 v1(21.59,21.08)
  BOTTOM w0.127: R292.1 R294.2 21.46,21.08 v1(21.59,21.08) R293.1
NETSB5_1: length 150.6
  TOP w0.127: v1(108.27,93.85) 110.3,91.82 115.95,91.82 122.17,85.6 122.17,79.5 114.68,72.01 v1(114.68,69.98) ; 92.84,149.35 92.84,150.24 v1(93.73,151.13) ; v1(119.18,26.49) 119.36,26.68 U23.G1
  L3_SIG w0.102: v1(119.18,26.49) 118.87,26.8 117.86,26.8 117.45,27.2 117.45,27.48 117.04,27.89 117.04,28.73 117.39,29.07 117.39,29.52 113.69,33.22 113.69,48.67 114.43,49.4 114.43,69.72 v1(114.68,69.98)
  BOTTOM w0.127: v1(108.27,93.85) 107.44,94.68 107.44,112.39 105.79,114.05 105.79,123.7 104.65,124.84 104.65,131.19 101.6,134.24 101.6,145.67 96.14,151.13 v1(93.73,151.13)
NETSB7_1: length 144.6
  TOP w0.127: SB7.1 106.68,143.69 106.71,143.66 v1(107.19,144.15) ; U23.E3 v2(118.11,28.33)
  L3_SIG w0.102: v2(118.11,28.33) 117.81,28.64 117.81,30.07 117.93,30.2 117.93,30.56 115.67,32.82 115.67,37.11 115.11,37.67 115.11,68.2 116.33,69.42 v1(116.33,75.82)
  BOTTOM w0.127: v1(107.19,144.15) 107.31,144.02 107.31,135.92 108.36,134.87 118.49,134.87 119.38,133.99 119.38,123.32 119.76,122.94 119.76,118.49 114.53,113.26 114.53,84.23 116.46,82.3 116.46,75.95 v1(116.33,75.82)
NETSB9_1: length 151.3
  TOP w0.127: U23.F2 v2(118.61,27.33) ; 91.19,140.59 91.69,140.08 92.08,140.08 92.62,139.53 101.26,139.53 v1(102.11,138.68) ; v1(108.27,94.74) 110.55,92.46 124.33,92.46 v1(125.22,93.34)
  L3_SIG w0.102: v1(125.22,93.34) 124.97,93.09 123.57,93.09 118.92,88.44 118.92,79.07 115.8,75.95 115.8,69.85 114.76,68.81 114.76,37.54 114.05,36.83 114.05,33.3 117.6,29.74 117.6,28.88 117.3,28.57 117.3,27.99 117.68,27.61 117.68,27.33 117.98,27.03 118.3,27.03 v2(118.61,27.33)
  BOTTOM w0.127: v1(108.27,94.74) 107.95,95.06 107.95,110.49 108.08,110.62 108.08,116.46 106.55,117.98 106.55,124.16 105.41,125.3 105.41,131.65 102.54,134.52 102.54,138.25 v1(102.11,138.68)
NETSB12_2: length 57.5
  TOP w0.127: 91.19,135 95.71,135 v1(96.14,135.43) ; U6.41 128.77,127.29 129.16,127.69 129.16,130.56 128.91,130.81 128.37,130.81 126.87,132.31 v1(126.87,143.13)
  L3_SIG w0.102: v1(96.14,135.43) 100.36,139.65 110.34,139.65 110.95,140.26 116.64,140.26 117.96,141.58 125.45,141.58 126.87,143 v1(126.87,143.13)
NETSB15_1: length 118.2
  TOP w0.127: v1(56.69,31.17) 56.69,31.83 56.26,32.26 56.26,36.71 56.51,36.96 U22.30 ; v1(16.13,98.17) 16.51,98.55 16.51,106.81 17.65,107.95 SB15.1
  L3_SIG w0.102: v1(56.69,31.17) 56.44,31.17 54.23,28.96 44.32,28.96 39.85,33.43 37.57,33.43 33.66,37.34 33.66,43.81 31.88,45.59 31.88,61.85 31.11,62.61 31.11,69.25 28.32,72.05 28.32,86.46 27.66,87.12 27.66,93.5 22.68,98.48 16.43,98.48 v1(16.13,98.17)
NETSB16_1: length 6.3
  TOP w0.127: U8.3 25.03,106.8 24.38,107.44 21.97,107.44 SB16.1
NETSB19_1: length 86.2
  TOP w0.127: v2(118.61,28.83) 118.36,28.58 U23.E4 ; SB19.1 125.6,96.14 v1(125.32,96.14)
  L3_SIG w0.102: v1(122.49,28) 121.84,28.65 118.79,28.65 v2(118.61,28.83)
  BOTTOM w0.127: v1(122.49,28) 123.47,28.98 123.47,31.39 124.71,32.64 124.71,40.39 131.83,47.5 131.83,60.45 124.13,68.15 124.13,95.17 125.09,96.14 v1(125.32,96.14)
NETSB25_2: length 135.4
  TOP w0.127: U25.3 123.78,14.82 123.19,14.22 123.19,13.84 122.94,13.59 120.14,13.59 v1(119.89,13.84) ; v1(2.92,6.99) 3.77,7.83 U26.3
  BOTTOM w0.127: SB25.2 120.14,14.1 v1(119.89,13.84) 118.05,13.84 116.33,15.56 71.31,15.56 63.06,7.31 52.26,7.31 47.23,2.29 33.02,2.29 25.1,10.21 16.46,10.21 15.14,8.89 4.83,8.89 v1(2.92,6.99)
NETSB26_1: length 139.1
  TOP w0.127: U26.4 5.63,7.83 v1(6.48,6.99) ; v1(128.52,14.1) 126.36,14.1 125.65,14.82 U25.4
  BOTTOM w0.127: v1(6.48,6.99) 7.87,8.38 15.62,8.38 16.94,9.7 24.21,9.7 32.26,1.65 47.5,1.65 52.2,6.35 63.75,6.35 72.26,14.86 115.95,14.86 117.47,13.34 127.76,13.34 v1(128.52,14.1) SB26.1
NETSB31_2: length 120.6
  TOP w0.127: v1(133.6,122.05) 133.6,122.04 U6.31
  BOTTOM w0.127: v1(133.6,122.05) 132.74,122.91 132.74,125.81 129.13,129.41 129.13,145.06 113.26,160.93 109.4,160.93 106.58,163.75 64.95,163.75 64.26,163.07 57.66,163.07 49.68,155.09 49.68,154.58 48.39,153.29 48.39,153.03 SB31.2
NETSB32_2: length 63.6
  TOP w0.127: v1(27.94,100.33) 28.2,100.59 U8.12
  L3_SIG w0.102: v1(27.94,100.33) 27.94,100.84 28.07,100.97 30.1,100.97 31.24,102.11 31.24,109.73 34.67,113.16 34.67,114.94 36.07,116.33 36.07,123.32 34.04,125.35 34.04,144.65 34.54,145.16 34.54,146.69 39.37,151.51 v1(39.5,151.51)
  BOTTOM w0.127: SB32.2 40.13,152.15 v1(39.5,151.51)
NETSB34_2: length 73.8
  TOP w0.127: U8.13 28.7,100.97 v1(29.34,100.33)
  L3_SIG w0.102: v1(43.31,149.22) 43.31,148.97 43.03,148.69 40.64,148.69 40.51,148.56 40.51,148.21 40.64,148.08 43.05,148.08 43.18,147.96 43.18,147.75 43.05,147.62 40.64,147.62 40.51,147.5 40.51,147.26 40.64,147.13 42.75,147.13 42.88,147.01 42.88,146.8 42.76,146.68 40.38,146.68 40.01,146.3 40.01,145.29 37.47,142.75 37.47,139.06 36.73,138.33 36.73,124.79 37.47,124.05 37.47,116.54 35.41,114.48 35.41,112.88 32.21,109.68 32.21,104.09 31.5,103.38 31.5,101.98 29.84,100.33 v1(29.34,100.33)
  BOTTOM w0.127: SB34.2 40.51,150.24 40.86,149.9 42.76,149.9 43.31,149.35 v1(43.31,149.22)
NETSB48_1: length 138.8
  TOP w0.127: U6.40 129.27,127.11 129.54,127.38 129.54,130.76 129.01,131.29 128.55,131.29 127.25,132.59 127.25,142.24 127.89,142.88 127.89,148.46 v1(127.25,149.1)
  BOTTOM w0.127: SB48.1 38.23,145.16 38.23,155.19 42.16,159.13 51.56,159.13 58.55,166.12 110.49,166.12 121.41,155.19 121.41,155.17 127.25,149.33 v1(127.25,149.1)
NETSB56_2: length 68.8
  TOP w0.127: v1(27.25,100.3) 27.25,101.17 27.7,101.61 U8.11
  L3_SIG w0.102: v1(43.43,137.67) 42.93,138.18 39.04,138.18 38.86,138 38.86,132.08 38.35,131.57 38.35,125.81 38.86,125.3 38.86,112.17 34.9,108.2 34.14,108.2 34.01,108.08 34.01,107.79 34,107.78 34,107.6 34.01,107.58 34.01,107.38 33.91,107.28 33.15,107.28 33.05,107.18 33.05,106.98 33.15,106.87 33.91,106.87 34.01,106.77 34.01,106.57 33.91,106.47 33.15,106.47 33.05,106.37 33.05,106.16 33.15,106.06 33.91,106.06 34.01,105.96 34.01,105.76 33.91,105.65 33.15,105.65 33.05,105.55 33.05,105.35 33.15,105.25 33.91,105.25 34.01,105.15 34.01,104.94 33.91,104.84 33.15,104.84 33.05,104.74 33.05,104.51 33.15,104.41 33.86,104.41 33.96,104.31 33.96,104.1 33.86,104 33.15,104 33.05,103.9 33.05,103.7 33.15,103.6 33.86,103.6 33.96,103.5 33.96,103.29 33.86,103.19 33.15,103.19 33.05,103.09 33.05,102.89 33.15,102.78 33.86,102.78 33.96,102.68 33.96,102.48 33.86,102.38 33.15,102.38 33.05,102.28 33.05,102.07 33.15,101.97 33.86,101.97 33.96,101.87 33.96,101.67 33.86,101.56 33.15,101.56 33.05,101.46 33.05,100.41 32.46,99.82 27.74,99.82 v1(27.25,100.3)
  BOTTOM w0.127: SB56.2 43.31,137.41 43.43,137.54 v1(43.43,137.67)
NETSB63_2: length 107.6
  TOP w0.127: v1(127.25,122.94) 127.25,123.57 128.27,124.58 U6.42
  L3_SIG w0.102: v1(127.25,122.94) 122.86,122.94 116.92,116.99 111.05,116.99 108.76,119.28 101.5,119.28 99.14,116.92 58.65,116.92 56.69,118.87 51.82,118.87 v1(51.31,118.36)
  BOTTOM w0.127: SB63.2 62.1,135.51 52.68,126.09 52.68,119.74 v1(51.31,118.36)
NETSB67_1: length 122.7
  TOP w0.127: v1(108.61,73.41) 108.46,73.25 108.46,60.37 130.22,38.61 U24.1
  BOTTOM w0.127: v1(108.61,73.41) 109.09,73.41 114.81,79.12 114.81,82.55 113.49,83.87 113.49,114.43 118.72,119.66 118.72,121.97 118.41,122.28 118.41,126.95 117.88,127.48 117.88,131.32 117.53,131.7 SB67.1
NETTP12_1: length 6.7
  TOP w0.127: TP12.1 133.35,115.95 133.35,118.62 132.93,119.04 U6.25
NETU22_15: length 79.9
  TOP w0.127: U23.G3 v2(119.61,28.33) ; U22.15 v1(61.95,31.9)
  L3_SIG w0.102: v2(119.61,28.33) 121.37,28.33 123.57,26.14 125.7,26.14 126.29,25.55 v1(126.29,24.77)
  BOTTOM w0.127: v1(126.29,24.77) 126.29,23.52 125.63,22.86 111,22.86 103.38,30.48 70.99,30.48 69.57,31.9 v1(61.95,31.9)
OSC_IN: length 11.5
  TOP w0.203: U21.5 37.22,28.12 36.32,27.22 C84.1 36.32,27.14 37.21,26.25 37.21,22.99 36.45,22.23 X6.2
OSC_OUT: length 11.2
  TOP w0.203: U21.6 37.72,28.1 38.61,27.22 C85.1 38.61,27.14 37.72,26.25 37.72,22.99 38.48,22.23 X6.1
PA0: length 41.5
  TOP w0.127: v5(74.01,141.69) U4.N3 ; CN5.15 43.18,147.07 v1(43.43,146.81)
  L3_SIG w0.102: v5(74.01,141.69) 72.7,141.69 71.98,140.97 68.4,140.97 67.51,140.08 65.91,140.08 64.9,141.1 63.63,141.1 62.61,142.11 59.94,142.11 59.05,143 51.59,143 49.17,145.41 46,145.41 45.01,146.41 44.6,146.41 44.2,146.81 v1(43.43,146.81)
  BOTTOM w0.127: SB48.2 SB46.2 SB44.2 42.42,146.3 42.93,146.3 v1(43.43,146.81)
PA1: length 37.9
  TOP w0.127: CN5.14 v1(44.7,148.34) ; U4.N2 v5(74.01,142.49)
  L3_SIG w0.102: v5(74.01,142.49) 73.57,142.93 72.92,142.93 72.44,143.41 71.78,143.41 71.5,143.13 67.74,143.13 66.47,144.4 63.12,144.4 61.95,145.57 52.5,145.57 49.94,148.13 44.91,148.13 v1(44.7,148.34)
  BOTTOM w0.127: SB33.2 SB39.2 45.59,149.22 v1(44.7,148.34)
PA2: length 38.1
  TOP w0.127: CN5.13 v1(43.43,148.34) ; U4.P2 v5(73.21,142.49)
  L3_SIG w0.102: v1(43.43,148.34) 44.15,147.62 49.78,147.62 52.27,145.14 61.75,145.14 62.89,143.99 66.37,143.99 67.56,142.8 71.63,142.8 71.75,142.67 73.03,142.67 v5(73.21,142.49)
  BOTTOM w0.127: 42.14,149.08 42.69,149.08 v1(43.43,148.34) 42.67,147.57 SB42.2
PA3: length 105.4
  TOP w0.127: v1(34.8,110.11) 34.92,110.11 R82.2 ; v1(44.83,145.8) CN5.18 49.15,145.8 50.7,144.25 64.8,144.25 65.99,143.05 70.82,143.05 71.78,142.09 U4.R2
  L3_SIG w0.102: v1(34.8,110.11) 35.1,110.11 35.35,110.36 35.35,110.5 34.55,111.31 34.55,111.48 34.66,111.6 34.83,111.6 35.64,110.79 35.79,110.79 35.93,110.94 35.93,111.08 35.1,111.91 35.1,112.08 35.21,112.2 35.38,112.2 36.22,111.37 36.36,111.37 36.5,111.51 36.5,111.65 35.79,112.37 35.79,114.25 37.8,116.26 37.8,124.31 37.08,125.02 37.08,138.15 37.8,138.86 37.8,142.65 38.1,142.95 42.81,142.95 42.93,143.07 42.93,143.24 42.81,143.36 39.12,143.36 38.99,143.48 38.99,143.69 39.12,143.81 43.19,143.81 43.31,143.93 43.31,144.1 43.19,144.22 39.87,144.22 39.75,144.34 39.75,144.51 39.87,144.63 43.06,144.63 43.18,144.75 43.18,144.91 43.06,145.03 40.63,145.03 40.51,145.15 40.51,145.32 40.63,145.44 42.81,145.44 42.93,145.56 42.93,145.73 42.81,145.85 40.64,145.85 40.51,145.97 40.51,146.18 40.64,146.3 43.94,146.3 44.45,145.8 v1(44.83,145.8)
PA4: length 54.6
  TOP w0.127: v1(43.41,143.26) CN5.21 38.79,143.26 37.95,142.42 v1(32.46,142.42) ; U4.N4 v5(74.01,140.89)
  L3_SIG w0.102: v5(74.01,140.89) 72.94,140.89 72.26,140.21 69.53,140.21 68.26,138.94 63.37,138.94 61.85,140.46 57.66,140.46 56.52,141.6 50.55,141.6 48.13,144.02 44.17,144.02 v1(43.41,143.26)
  BOTTOM w0.127: JP3.1 29.26,142.42 v1(32.46,142.42) ; v1(43.41,143.26) 44.04,142.62 45.21,142.62 45.59,143 SB47.2
PA5: length 107.6
  TOP w0.127: R113.2 v1(30.73,100.33) ; v1(44.83,141.99) CN5.24 49.15,141.99 49.53,141.6 64.52,141.6 66.04,140.08 67.31,140.08 68.15,140.92 73.18,140.92 73.61,140.49 U4.P4
  L3_SIG w0.102: v1(30.73,100.33) 32.46,100.33 32.59,100.46 32.59,108.97 32.72,109.09 34.54,109.09 36.86,111.4 36.86,114.76 38.18,116.08 38.18,124.61 37.59,125.2 37.59,131.95 38.07,132.44 38.07,134.65 37.41,135.31 37.41,135.51 37.52,135.62 38.07,135.62 38.18,135.72 38.18,135.92 38.07,136.02 37.52,136.02 37.41,136.12 37.41,136.33 37.52,136.43 38.07,136.43 38.18,136.53 38.18,136.73 38.07,136.83 37.52,136.83 37.41,136.94 37.41,137.14 37.52,137.24 38.07,137.24 38.18,137.34 38.18,137.55 38.07,137.65 37.52,137.65 37.41,137.75 37.41,137.95 37.52,138.05 38.07,138.05 38.18,138.16 38.18,141.55 38.23,141.6 42.67,141.6 42.8,141.73 42.8,142.04 42.68,142.16 38.2,142.16 38.1,142.27 38.1,142.49 38.23,142.62 44.2,142.62 44.32,142.75 44.32,143.56 44.45,143.69 47.5,143.69 47.62,143.56 47.62,142.49 47.5,142.37 44.96,142.37 44.83,142.24 v1(44.83,141.99)
PA6: length 170.1
  TOP w0.102: 71.63,141.73 71.65,141.71 73.19,141.71 U4.P3
  TOP w0.127: R15.2 108.08,159.77 v1(108.08,160.27) ; v1(44.83,144.53) CN5.20 49.5,144.53 50.27,143.76 64.52,143.76 65.66,142.62 70.61,142.62 71.5,141.73 71.63,141.73 ; v1(151.1,141.1) 151.1,141.08 150.75,140.72 150.75,140.71 150.73,140.69 CN4.33
  L3_SIG w0.102: v1(108.08,160.27) 118.24,160.27 119.05,159.46 125.65,159.46 126.42,158.7 147.5,158.7 149.35,156.84 149.35,146.43 149.94,145.84 150.83,145.84 151.26,145.41 151.26,144.4 151.1,144.25 150.85,143.99 150.85,143.61 151.51,142.95 151.51,141.49 151.12,141.1 v1(151.1,141.1)
  BOTTOM w0.127: v1(108.08,160.27) 105.56,162.79 87,162.79 86.36,162.15 85.39,162.15 85.09,162.46 66.17,162.46 63.35,159.64 59.69,159.64 52.84,152.79 52.84,152.77 52.58,152.51 52.57,152.51 50.85,150.8 50.85,147.88 49.78,146.81 45.34,146.81 45.09,146.56 44.7,146.56 44.07,145.92 44.07,145.29 v1(44.83,144.53)
PA7: length 32.1
  TOP w0.127: v1(44.83,143.26) CN5.22 64.31,143.26 65.38,142.19 70.54,142.19 71.44,141.29 U4.R3
  BOTTOM w0.127: SB43.2 SB45.2 v1(44.83,143.26)
PA8: length 49.3
  TOP w0.127: U4.F15 80.01,131.45 81.33,130.12 81.33,127.84 82.8,126.36 84.48,126.36 84.84,126.73 v1(84.84,127.09) ; v1(113.49,124.74) 114.02,124.21 CN6.52
  L3_SIG w0.102: v1(84.84,127.09) 85.08,127.09 86.1,126.06 88.49,126.06 88.9,126.47 103.68,126.47 106.88,129.67 110.49,129.67 113.03,127.13 113.03,125.2 v1(113.49,124.74)
  BOTTOM w0.127: v1(113.49,124.74) 114.27,123.95 SB80.2 SB77.2 SB75.2
PA9: length 41.2
  TOP w0.127: v1(82.83,127.86) 82.78,127.8 82.38,127.8 82.02,128.16 82.02,130.47 80.81,131.68 U4.E15 ; CN6.43 v1(112.01,129.29)
  L3_SIG w0.102: v1(82.83,127.86) 82.95,127.97 85.19,127.97 86.48,126.69 88.08,126.69 88.42,127.03 103.05,127.03 106.32,130.3 110.74,130.3 111.76,129.29 v1(112.01,129.29)
  BOTTOM w0.127: v1(112.01,129.29) SB72.2 R253.1
PA10: length 279
  TOP w0.127: v1(45.69,117.07) 45.21,116.59 38.61,116.59 34.54,120.65 30.73,120.65 29.34,119.25 v1(19.94,119.25) ; v1(9.02,103.63) 8.89,103.5 R107.2 ; v5(82.42,128.34) 82.42,130.9 81.63,131.69 U4.D15 ; JP15.2 69.6,30.1 v1(76.2,36.7) ; v1(113.28,129.29) CN6.44
  L3_SIG w0.102: v1(45.69,117.07) 45.95,117.32 46.41,117.32 49.73,120.65 57.91,120.65 59.82,118.75 97.16,118.75 99.31,120.9 108.66,120.9 110.46,122.71 112.12,122.71 112.6,122.22 112.98,122.22 114.07,123.32 114.07,128.6 113.39,129.29 v1(113.28,129.29) 112.67,129.29 112.17,129.79 111.73,129.79 110.87,130.66 106.2,130.66 102.87,127.33 88.21,127.33 87.86,126.98 86.79,126.98 85.45,128.31 82.44,128.31 v5(82.42,128.34)
  BOTTOM w0.127: v1(9.02,103.63) 9.02,107.06 10.16,108.2 11.68,108.2 14.22,110.74 14.22,116.2 17.27,119.25 v1(19.94,119.25) ; v1(76.2,36.7) 76.2,38.86 74.17,40.89 74.17,42.82 72.14,44.86 72.14,46.74 73.66,48.26 73.66,51.31 72.29,52.68 67.67,52.68 65.89,54.46 65.89,63.27 57.28,71.88 57.28,83.31 48.77,91.82 48.77,112.65 47.37,114.05 47.37,115.39 v1(45.69,117.07)
PA11: length 202.8
  TOP w0.127: U4.C15 83.24,130.85 84.02,130.85 84.6,130.27 84.6,128.86 85.27,128.19 85.53,127.93 87.17,127.93 v1(87.31,127.79) ; v1(111.94,130.56) CN6.41
  TOP w0.155: v1(9.23,99.04) 9.09,99.18 8.56,99.18 D5.D3
  L3_SIG w0.102: v1(111.94,130.56) 111.46,131.04 105.74,131.04 102.71,128 87.52,128 v1(87.31,127.79)
  L3_SIG w0.13: v1(111.94,130.56) 111.99,130.51 112.5,130.51 112.98,130.99 114.38,130.99 115.19,130.18 115.19,123.09 113.44,121.34 110.47,121.34 109.23,120.09 100.31,120.09 97.97,117.75 59.05,117.75 57.35,119.46 50.63,119.46 48.26,117.09 48.26,114.35 38.43,104.52 38.43,103.02 33.43,98.02 25.62,98.02 24.02,99.62 10.41,99.62 9.97,99.18 9.37,99.18 v1(9.23,99.04)
  BOTTOM w0.127: v1(9.23,99.04) 8.89,98.7 R281.2 ; v1(111.94,130.56) 112.55,129.95 112.55,128.27 112.8,128.02 116.59,128.02 117.83,126.77 117.83,121.95 118.11,121.67 118.11,120.02 112.42,114.33 112.42,106.32 JP9.1
  BOTTOM w0.155: v1(111.94,130.56) 111.68,130.81 110.87,130.81
PA12: length 42.1
  TOP w0.127: CN6.42 114.05,130.56 v1(112.78,131.83) ; v1(87.26,128.5) 87.06,128.3 85.69,128.3 84.97,129.02 84.97,130.43 84.17,131.23 83.67,131.23 U4.B15
  L3_SIG w0.102: v1(112.78,131.83) 112.27,131.32 105.54,131.32 102.53,128.31 87.45,128.31 v1(87.26,128.5)
  BOTTOM w0.127: SB66.2 SB67.2 SB71.2 114.43,130.18 v1(112.78,131.83)
PA13: length 262.9
  TOP w0.127: U21.25 40.72,38.82 40.43,39.12 v1(40.01,39.12) 39.72,38.83 U21.27 ; R80.2 126.49,111.12 v1(127,110.62) ; v1(150.75,125.73) 150.24,126.24 150.24,127.38 149.61,128.02 147.57,128.02 145.54,130.05 145.54,133.1 144.4,134.24 135.76,134.24 132.23,137.77 v1(132.23,141.38) ; v1(113.49,132.41) 114.07,131.83 CN6.40 ; v1(84.84,131.44) 84.59,131.69 U4.A15
  L3_SIG w0.102: v1(84.84,131.44) 85.22,131.06 85.6,131.06 85.85,131.32 86.79,131.32 87.68,130.43 95.78,130.43 98.25,132.89 113,132.89 v1(113.49,132.41) 119.48,132.41 128.45,141.38 v1(132.23,141.38) ; v1(150.75,125.73) 150.75,120.82 149.95,120.02 145.63,120.02 142.07,116.46 140.42,116.46 136.74,112.78 133.1,112.78 130.94,110.62 v1(127,110.62) 126.49,110.11 126.49,105.92 127.81,104.6 127.81,101.96 127.36,101.5 126.11,101.5 122.91,98.3 121.03,98.3 117.89,95.16 117.89,93.89 111.33,87.33 111.33,77.47 109.04,75.18 109.04,73.13 84.25,48.34 83.13,48.34 81.79,46.99 81.79,45.97 80.39,44.58 60.71,44.58 56.9,40.77 51.92,40.77 49.53,38.38 49.53,34.67 47.88,33.02 44.58,33.02 43.99,33.6 43.23,33.6 42.16,34.67 42.16,35.69 40.01,37.85 v1(40.01,39.12)
PA14: length 263.9
  TOP w0.127: v1(127,109.6) 126.75,109.86 R87.2 ; U21.26 40.22,37.05 v1(39.88,36.7) ; U21.15 44.22,31.9 v1(44.7,32.38) ; v1(150.75,126.75) 150.75,127.64 149.99,128.4 147.83,128.4 146.05,130.18 146.05,133.86 145.03,134.87 135.89,134.87 132.72,138.05 132.72,141.88 v1(132.18,142.42) ; U4.A14 86.6,132.49 86.9,132.18 v1(86.97,132.18) ; CN6.36 113.67,134.37 v1(112.78,133.48)
  L3_SIG w0.102: v1(150.75,126.75) 151.26,126.24 151.26,120.97 150.05,119.76 145.73,119.76 142.18,116.2 140.53,116.2 136.84,112.52 133.35,112.52 130.96,110.13 127.53,110.13 v1(127,109.6) 126.9,109.5 126.9,106.15 128.12,104.93 128.12,101.75 127.58,101.22 126.26,101.22 122.91,97.87 121.23,97.87 118.34,94.97 118.34,93.72 111.58,86.97 111.58,77.29 109.45,75.16 109.45,73.05 80.59,44.2 60.91,44.2 57.1,40.39 52.02,40.39 49.89,38.25 49.89,34.52 47.6,32.23 44.86,32.23 v1(44.7,32.38) 43.81,33.27 42.95,33.27 40.51,35.71 40.51,36.07 v1(39.88,36.7) ; v1(132.18,142.42) 128.88,142.42 119.94,133.48 v1(112.78,133.48) 96.09,133.48 94.46,131.85 90.45,131.85 89.79,131.19 87.96,131.19 v1(86.97,132.18)
PA15: length 259.1
  TOP w0.127: v1(112.78,137.16) 113.41,136.53 113.92,136.53 114.3,136.91 CN6.32 ; v1(43.56,32.38) 43.04,32.9 U21.17 ; v1(151.7,126.75) 151.64,126.81 151.64,127.82 150.3,129.16 148.34,129.16 146.81,130.68 146.81,134.87 145.67,136.02 136.4,136.02 133.99,138.43 133.99,141.73 v1(133.35,142.37) ; v1(128.27,108.33) 128.14,108.33 127.13,107.31 R93.2 ; U4.A13 v5(86.23,133.29)
  L3_SIG w0.102: v1(43.56,32.38) 44.37,31.57 49.1,31.57 50.77,33.25 50.77,37.06 52.2,38.48 53.72,38.48 54.99,39.75 56.26,39.75 56.9,39.12 61.34,39.12 62.99,40.77 78.59,40.77 110.62,72.8 110.62,74.73 114.05,78.16 114.05,80.52 114.91,81.38 114.91,88.62 125.43,99.14 126.72,99.14 129.16,101.58 129.16,107.44 v1(128.27,108.33) 128.27,108.71 128.59,109.03 131,109.03 133.73,111.76 137.16,111.76 140.84,115.44 142.49,115.44 146.05,119 150.37,119 152.27,120.9 152.27,126.11 151.7,126.68 v1(151.7,126.75) ; v1(133.35,142.37) 132.72,143 128.85,143 122,136.14 113.79,136.14 v1(112.78,137.16) 107.7,137.16 106.9,136.36 98.31,136.36 94.79,132.84 86.68,132.84 v5(86.23,133.29)
PAR_D0: length 135.9
  TOP w0.127: v1(108.04,128.85) 107.35,129.54 JP5.3 ; v1(147.96,144.86) 148.79,145.69 CN4.23 ; v1(79.76,128.59) 79.69,128.59 78.82,129.46 78.82,131.27 U4.H15 ; v1(120.14,155.32) 119.89,155.07 119.89,143.26 118.29,141.66 118.29,121.34 117.35,120.4 CN6.58 114.3,120.4 112.81,121.88 v1(112.81,122.71)
  L3_SIG w0.102: v1(120.14,155.32) 121.03,155.32 121.41,154.94 125.98,154.94 126.75,154.18 128.52,154.18 130.43,156.08 143.64,156.08 146.1,153.62 146.1,146.28 147.52,144.86 v1(147.96,144.86) ; v1(112.81,122.71) 112.81,122.72 112.39,123.14 112.39,126.87 110.41,128.85 v1(108.04,128.85) 107.37,128.18 107.37,126.52 106.38,125.53 89.46,125.53 88.74,124.81 87.05,124.81 86.51,125.35 85.8,125.35 84.86,126.29 82.75,126.29 80.45,128.59 v1(79.76,128.59)
  BOTTOM w0.127: SB82.1 113.16,122.43 112.88,122.71 v1(112.81,122.71)
PAR_D1: length 186.6
  TOP w0.127: U4.G15 79.27,131.62 79.27,129.78 v1(79.81,129.24) ; CN1.7 94.61,166.65 94.61,159.87 v1(97,157.48) ; CN4.24 152.17,145.41 151.64,145.41 150.77,144.55 v1(150.47,144.55) ; v1(112.83,123.37) 113.59,122.61 113.59,122.38 114.3,121.67 CN6.56 116.46,121.67 117.93,123.14 117.93,141.94 119.38,143.38 119.38,155.57 v1(119.76,155.96)
  L3_SIG w0.102: v1(119.76,155.96) 120.14,156.34 122.3,156.34 123.06,155.57 125.6,155.57 126.62,156.59 143.76,156.59 146.46,153.9 146.46,147.17 146.94,146.69 147.37,146.69 149.51,144.55 v1(150.47,144.55) ; v1(79.81,129.24) 79.9,129.15 80.43,129.15 82.98,126.59 85.17,126.59 86.04,125.73 88.65,125.73 89.05,126.14 104.04,126.14 107.24,129.34 110.44,129.34 112.65,127.13 112.65,123.55 v1(112.83,123.37)
  BOTTOM w0.127: R277.1 113.7,120.9 112.37,122.23 112.37,122.91 v1(112.83,123.37) 112.83,123.42 112.88,123.47 112.88,125.55 111.43,127 107.75,127 107.29,127.46 107.29,132.97 104.8,135.46 104.8,152.43 100.81,156.41 100.2,156.41 98.97,157.65 97.17,157.65 v1(97,157.48)
PAR_D2: length 140.2
  TOP w0.127: v1(150.5,145.18) 150.47,145.16 150.2,145.16 149.74,144.69 CN4.25 ; v1(106.27,126.09) 106.2,126.01 106.2,125.2 107.19,124.21 CN6.51 ; v1(87.24,125.29) 86.9,125.29 86.21,125.98 82.63,125.98 80.98,127.63 80.98,130.1 79.61,131.46 79.61,132.09 U4.G14
  L3_SIG w0.102: v1(87.24,125.29) 88.71,125.29 89.26,125.83 106.02,125.83 v1(106.27,126.09) ; v1(98.93,155.57) 99.44,156.08 102.92,156.08 103.5,156.67 108.66,156.67 110.24,158.24 124.49,158.24 124.79,157.94 145.47,157.94 148.62,154.78 148.62,146.27 149.71,145.18 v1(150.5,145.18)
  BOTTOM w0.127: v1(98.93,155.57) 100.08,154.43 100.61,154.43 103.4,151.64 103.4,134.77 106.17,132 106.17,126.19 v1(106.27,126.09) 106.27,125.76 108.08,123.95 SB81.1 SB78.1
PAR_D3: length 90.8
  TOP w0.127: U4.F14 80.39,132.11 80.39,131.51 81.68,130.22 81.68,127.99 82.32,127.36 v1(83.32,127.36) ; v1(151.28,143.81) 151.28,143.89 152.08,144.69 CN4.26 ; CN6.46 114.07,128.02 113.56,128.52 v1(113.28,128.52)
  L3_SIG w0.102: v1(83.32,127.36) 83.59,127.63 84.96,127.63 86.24,126.34 88.24,126.34 88.62,126.72 103.3,126.72 106.55,129.97 110.59,129.97 112.04,128.52 v1(113.28,128.52) ; v1(151.28,143.81) 151.28,143.64 151.74,143.18 151.74,140.77 151.47,140.5 145.97,140.5 145.22,139.75 128.07,139.75 118.62,130.3 v1(117.35,130.3)
  BOTTOM w0.127: v1(113.28,128.52) 114.43,128.52 R252.2 114.94,129.03 115.34,129.03 115.6,129.29 116.84,129.29 117.35,129.79 v1(117.35,130.3)
